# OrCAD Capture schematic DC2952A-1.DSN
size Custom; title: -20V, 200mA, ULTRALOW NOISE,; rev: 1; note: DC2952A
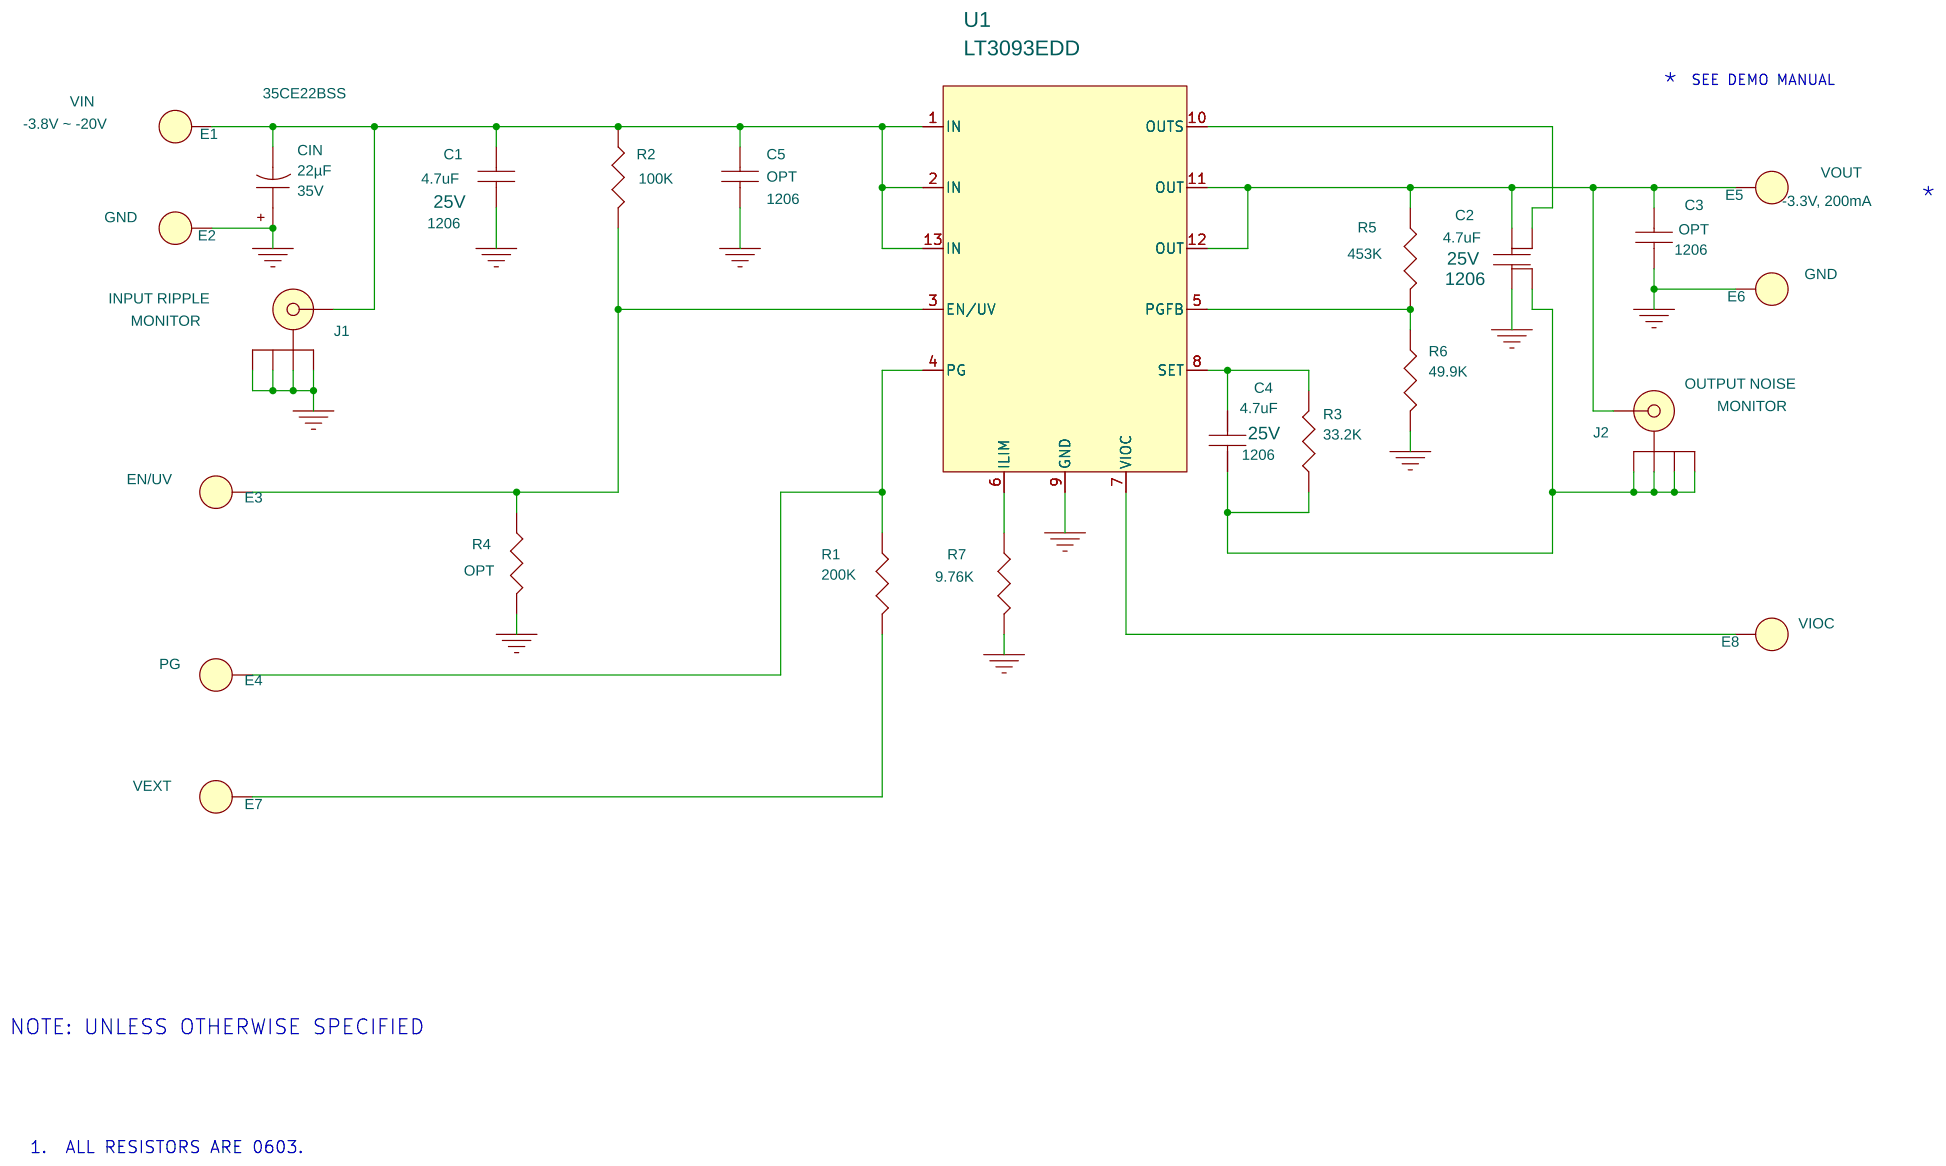
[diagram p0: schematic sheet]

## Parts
C1  4.7uF  [1206]
C2  4.7uF  [1206-SP]
C3  OPT  [1206]
C4  4.7uF  [1206]
C5  OPT  [1206]
CIN  22µF  [CAP-CE-5X5.4]
E1  VIN  [MM/2501]
E2  GND  [MM/2501]
E3  EN/UV  [MM/2501]
E4  PG  [MM/2501]
E5  -3.3V, 200mA  [MM/2501]
E6  GND  [MM/2501]
E7  VEXT  [MM/2501]
E8  VIOC  [MM/2501]
J1  MONITOR  [BNC5]
J2  MONITOR  [BNC5]
R1  200K  [0603]
R2  100K  [0603]
R3  33.2K  [0603]
R4  OPT  [0603]
R5  453K  [0603]
R6  49.9K  [0603]
R7  9.76K  [0603]
U1  LT3093EDD  [DFN-12PIN]

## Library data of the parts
C1 C4 = CAP_NP: 1ST PART FIELD: 25V
C2 = CAP_NP_1: 1ST PART FIELD: 25V; 2nd Part Field: 1206
C3 = CAP_NP
C5 = CAP_NP: 1ST PART FIELD: 50V; 2nd Part Field: 10uF
CIN = 50CE10BSS: 1st Part Field: 35V; 5TH PART FIELD: 35CE22BSS
E1 = MillMax-2501_1: 1ST PART FIELD: *; Value1: -3.8V ~ -20V
E2-E4 E6-E8 = MillMax-2501_1
E5 = MillMax-2501_1: VALUE1: VOUT
J1 = BNC_0: 1ST PART FIELD: INPUT RIPPLE
J2 = BNC_0: 1ST PART FIELD: OUTPUT NOISE
R1-R7 = R: V: 1%
U1 = LT3042EDD_5

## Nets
GND: C1.2 C2.1 C3.2 C5.2 CIN.1 E2.1 E6.1 J1.2 J1.3 J1.4 J1.5 R4.2 R6.2 R7.2 U1.9(GND)
N16788420: C1.1 C5.1 CIN.2 E1.1 J1.1 R2.1 U1.1(IN) U1.2(IN) U1.13(IN)
N16788606: E4.1 R1.2 U1.4(PG)
N16788632: C4.1 R3.2 U1.8(SET)
N16788700: C2.4 C3.1 E5.1 J2.1 R5.1 U1.11(OUT) U1.12(OUT)
N16788734: C2.3 C4.2 J2.2 J2.3 J2.4 J2.5 R3.1
N16788758: R5.2 R6.1 U1.5(PGFB)
N16831703: E3.1 R2.2 R4.1 U1.3(EN/UV)
N16883314: C2.2 U1.10(OUTS)
N16887303: E7.1 R1.1
N16887322: E8.1 U1.7(VIOC)
N16887886: R7.1 U1.6(ILIM)

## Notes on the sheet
- *
- SEE DEMO MANUAL
- *
- NOTE: UNLESS OTHERWISE SPECIFIED
- 1.  ALL RESISTORS ARE 0603.
